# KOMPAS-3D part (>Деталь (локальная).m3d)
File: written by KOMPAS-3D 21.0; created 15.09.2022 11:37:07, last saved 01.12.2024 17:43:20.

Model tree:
1. Эскиз:1
2. Эскиз:2
3. Эскиз:7
4. Спираль:3
     Число витков = 2; Высота = 30; Диаметр 1 = 5.05; Диаметр 2 = 10; Угол = 270
5. Эскиз:8
6. Эскиз:9
7. Эскиз:10
8. По кривой
     Число витков = 3; Шаг = 5; Высота = 15; Диаметр 1 = 4; Диаметр 2 = 10
9. Перпендикулярная плоскость:4
10. Эскиз:12
11. Элемент по траектории:3
12. Перпендикулярная плоскость:5
13. Эскиз:13
14. Элемент по траектории:4
15. Массив по концентрической сетке:1  (with: Элемент по траектории:4, Эскиз:2, Эскиз:1, Спираль:3, Эскиз:13)  (4 pattern instances)
     Шаг 2 = 180
16. Спираль:4
     Число витков = 3; Шаг = 40; Высота = 120; Диаметр 1 = 4; Диаметр 2 = 10; Угол = 90
17. Перпендикулярная плоскость:3
18. Эскиз:11
19. Элемент по траектории:2

Expressions: d*3; d*1.01
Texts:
  Размер дуги окружности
